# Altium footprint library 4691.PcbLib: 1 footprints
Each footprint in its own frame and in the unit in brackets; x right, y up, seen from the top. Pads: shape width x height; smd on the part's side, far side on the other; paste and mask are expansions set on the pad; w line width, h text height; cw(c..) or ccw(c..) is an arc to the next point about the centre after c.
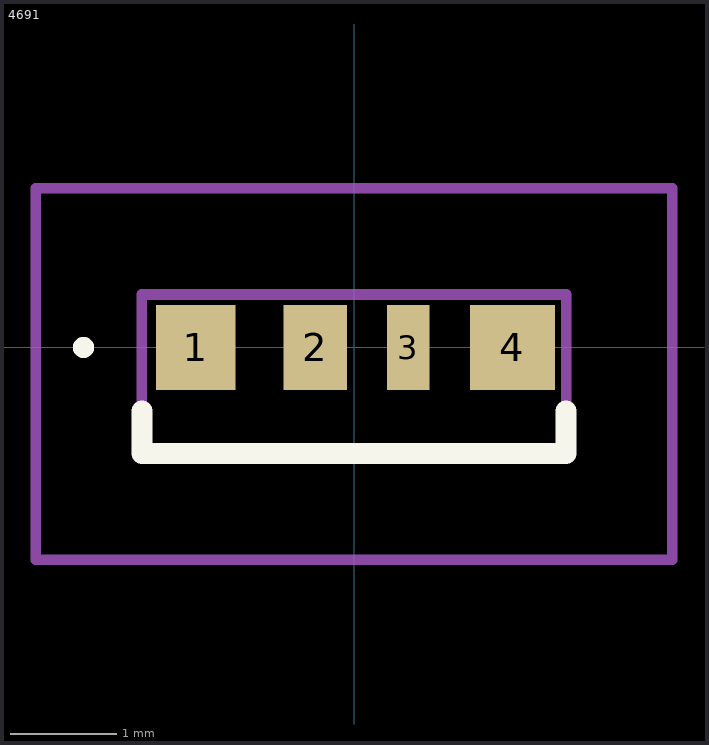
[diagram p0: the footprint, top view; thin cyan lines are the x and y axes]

## 4691 [mm]
pads (4):
  rect 0.75x0.8 smd: 1(-1.492,0)
  rect 0.6x0.8 smd: 2(-0.367,0)
  rect 0.4x0.8 smd: 3(0.513,0)
  rect 0.8x0.8 smd: 4(1.493,0)
Top Overlay:
  lines w0.1: -2.6,0 -2.6,0 ; -2.6,0 ccw(c-2.55,0) -2.5,0 ; -2.6,0 cw(c-2.55,0) -2.5,0 ; -2.5,0 -2.5,0
  lines w0.2: -2,-0.6 -2,-1 2,-1 2,-0.6
Mechanical 15:
  lines w0.1: -2,-1 2,-1 2,0.5 -2,0.5 -2,-1
Mechanical 20:
  lines w0.1: -3,-2 3,-2 3,1.5 -3,1.5 -3,-2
